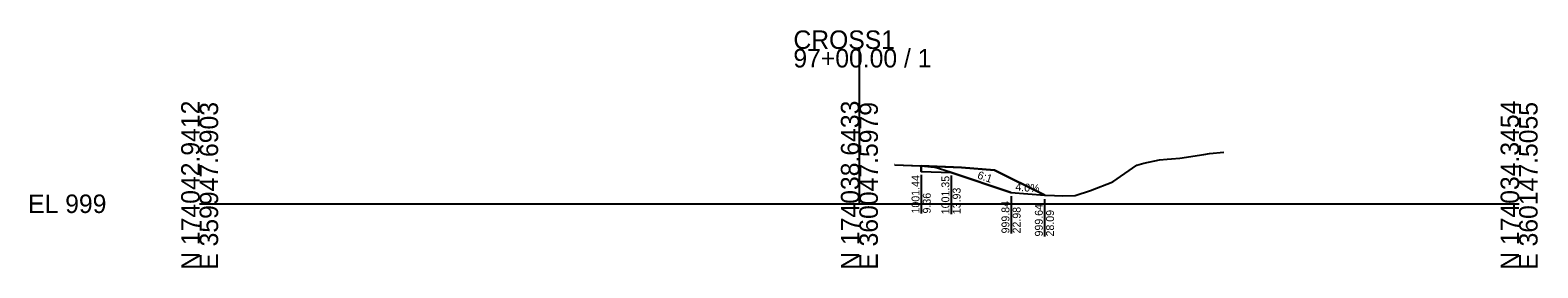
# Model space of a CAD drawing. Extents: x -26 to 1403, y -10 to 11027.
# Drawn here: x 1174.3 to 1402.8, y 490.3 to 526.3 of the extents above; entities that cross this region are included whole.
import ezdxf

# ---------------------------------------------------------------- set-up
doc = ezdxf.new("R2010")
doc.units = 0
for name, color, linetype in [('Default', 7, 'Continuous'), ('P_E_XS_Ground', 7, 'Continuous'), ('P_XS', 7, 'Continuous'), ('P_XS_EAR_CommonGrnd', 7, 'Continuous'), ('P_XS_Lane', 7, 'Continuous'), ('P_XS_Rock', 7, 'Continuous')]:
    doc.layers.add(name, color=color, linetype=linetype)

msp = doc.modelspace()

# ---------------------------------------------------------------- linework, layer by layer
at = {"layer": 'Default'}
for p, q in [((1300, 500), (1300, 523.43)), ((1200, 500), (1300, 500)), ((1300, 500), (1400, 500))]:
    msp.add_line(p, q, dxfattribs=at)
at = {"layer": 'P_E_XS_Ground'}
for p, q in [((1348.57, 506.91), (1352.22, 507.46)), ((1352.22, 507.46), (1353.08, 507.61)), ((1353.08, 507.61), (1355.26, 507.81)), ((1305.36, 505.88), (1305.3, 505.89)), ((1305.36, 505.88), (1315.5, 505.48)), ((1315.5, 505.48), (1320.5, 505.08)), ((1320.5, 505.08), (1328.09, 501.28)), ((1338.41, 503.3), (1342.03, 505.82)), ((1342.03, 505.82), (1343.12, 506.15)), ((1343.12, 506.15), (1345.5, 506.66)), ((1345.5, 506.66), (1346.66, 506.73)), ((1346.66, 506.73), (1347.31, 506.81)), ((1347.31, 506.81), (1348.57, 506.91)), ((1335.02, 501.99), (1338.41, 503.3)), ((1328.09, 501.28), (1329.56, 501.27)), ((1329.56, 501.27), (1330.84, 501.19)), ((1330.84, 501.19), (1332.7, 501.26)), ((1332.7, 501.26), (1335.02, 501.99))]:
    msp.add_line(p, q, dxfattribs=at)
at = {"layer": 'P_XS'}
for p, q in [((1305.36, 505.88), (1309.36, 505.72)), ((1309.36, 505.72), (1311.36, 505.56)), ((1313.93, 504.71), (1311.36, 505.56))]:
    msp.add_line(p, q, dxfattribs=at)
at = {"layer": 'P_XS_EAR_CommonGrnd'}
msp.add_lwpolyline([(1322.98, 501.69), (1328.09, 501.28), (1320.5, 505.08), (1315.5, 505.48), (1309.36, 505.72), (1309.36, 504.89), (1313.93, 504.71)], close=True, dxfattribs=at)
at = {"layer": 'P_XS_Lane'}
for p, q in [((1309.36, 504.89), (1309.36, 505.72)), ((1309.36, 504.89), (1313.93, 504.71)), ((1322.98, 501.69), (1313.93, 504.71)), ((1322.98, 501.69), (1328.09, 501.28))]:
    msp.add_line(p, q, dxfattribs=at)
at = {"layer": 'P_XS_Rock'}
for p, q in [((1309.36, 504.39), (1309.36, 498.53)), ((1313.89, 504.28), (1313.89, 498.42)), ((1322.99, 501.14), (1322.99, 495.51)), ((1328.05, 500.68), (1328.05, 495.05))]:
    msp.add_line(p, q, dxfattribs=at)

# ---------------------------------------------------------------- texts
at = {"layer": 'Default'}
for s, p in [('CROSS1', (1290, 523.43)), ('97+00.00 / 1', (1290, 520.63)), ('EL 999', (1174, 498.6))]:
    msp.add_text(s, height=2.8, dxfattribs=at).set_placement(p)
for s, p in [('N 174042.9412', (1200, 490)), ('E 359947.6903', (1202.8, 490)), ('N 174038.6433', (1300, 490)), ('E 360047.5979', (1302.8, 490)), ('N 174034.3454', (1400, 490)), ('E 360147.5055', (1402.8, 490))]:
    msp.add_text(s, height=2.8, rotation=90, dxfattribs=at).set_placement(p)
at = {"layer": 'P_XS_Rock'}
for s, rotation, p in [('1001.44', 90, (1309.11, 498.53)), ('1001.35', 90, (1313.64, 498.42)), ('6:1', 341.5651, (1317.79, 503.85)), ('4.0%', 355.4261, (1323.62, 501.99)), ('9.36', 90, (1310.81, 498.53)), ('13.93', 90, (1315.34, 498.42)), ('999.84', 90, (1322.74, 495.51)), ('22.98', 90, (1324.44, 495.51)), ('999.64', 90, (1327.8, 495.05)), ('28.09', 90, (1329.5, 495.05))]:
    msp.add_text(s, height=1.2, rotation=rotation, dxfattribs=at).set_placement(p)

doc.saveas('drawing.dxf')
